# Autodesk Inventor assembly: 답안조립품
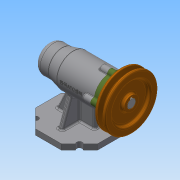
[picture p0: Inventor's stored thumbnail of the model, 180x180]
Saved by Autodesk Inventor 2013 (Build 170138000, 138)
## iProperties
Created: 2019-12
Part Number: 답안조립품
Document SubType Name: Assembly
Designer: Administrator
Author: Administrator
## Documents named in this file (12)
- C:\Users\Administrator\Desktop\491204V1024\답안조립품.iam
- C:\Users\Administrator\Desktop\491204V1024\본체.ipt
- C:\Users\Administrator\Desktop\491204V1024\베어링 51202.ipt
- C:\Users\Administrator\Desktop\491204V1024\어댑터슬리브.ipt
- C:\Users\Administrator\Desktop\491204V1024\볼트 M4.ipt
- C:\Users\Administrator\Desktop\491204V1024\베어링 6004.ipt
- C:\Users\Administrator\Desktop\491204V1024\축.ipt
- C:\Users\Administrator\Desktop\491204V1024\커버.ipt
- C:\Users\Administrator\Desktop\491204V1024\오일 실.ipt
- C:\Users\Administrator\Desktop\491204V1024\멈춤나사 M3.ipt
- C:\Users\Administrator\Desktop\491204V1024\키 5 x 5 x 16.ipt
- C:\Users\Administrator\Desktop\491204V1024\V벨트풀리.ipt
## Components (1 placed, 1 different names)
1. V벨트풀리:1 — 각도:2
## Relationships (1: Angle 1)
- 각도:2 [Angle]: V벨트풀리:1
